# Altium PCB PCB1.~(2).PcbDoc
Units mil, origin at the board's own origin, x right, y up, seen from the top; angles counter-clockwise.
Board outline 6000 x 4000 mil, 2 copper layers (Top Layer, Bottom Layer); 19 components, 17 nets, 64 pads, 0 vias.
Unrouted connection lines stored in the file: 41.
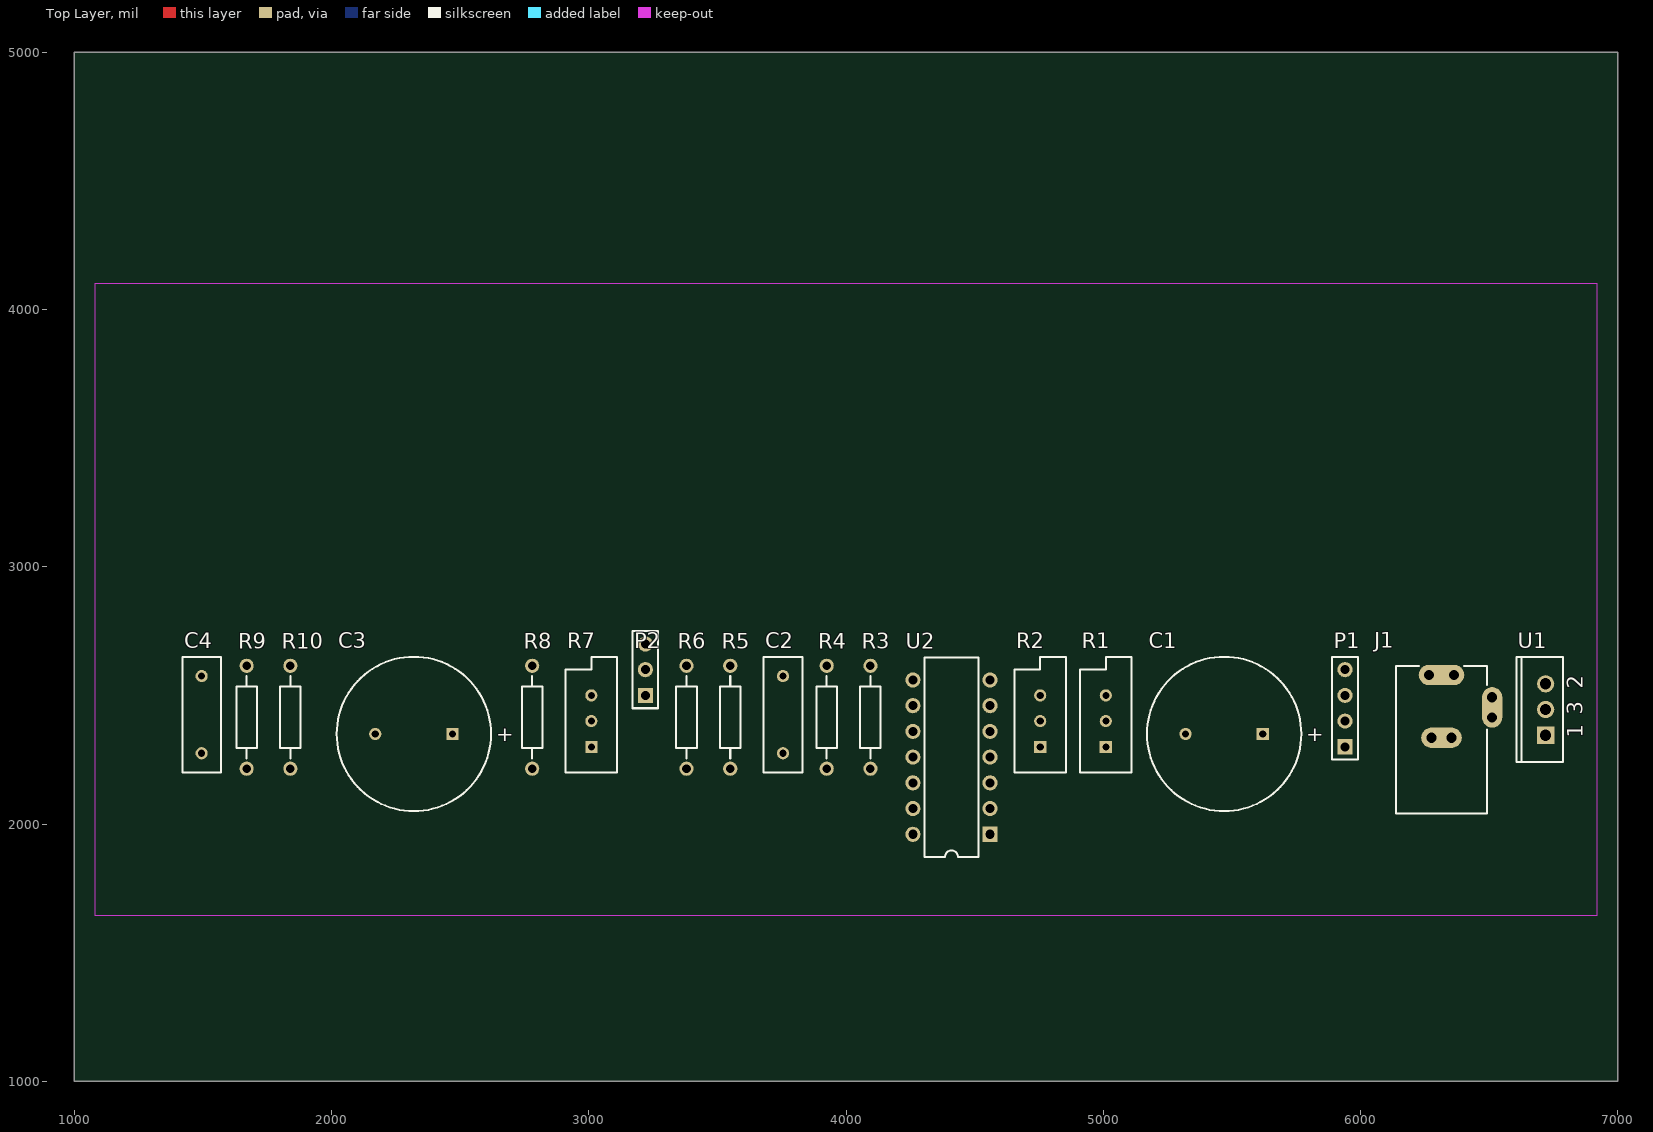
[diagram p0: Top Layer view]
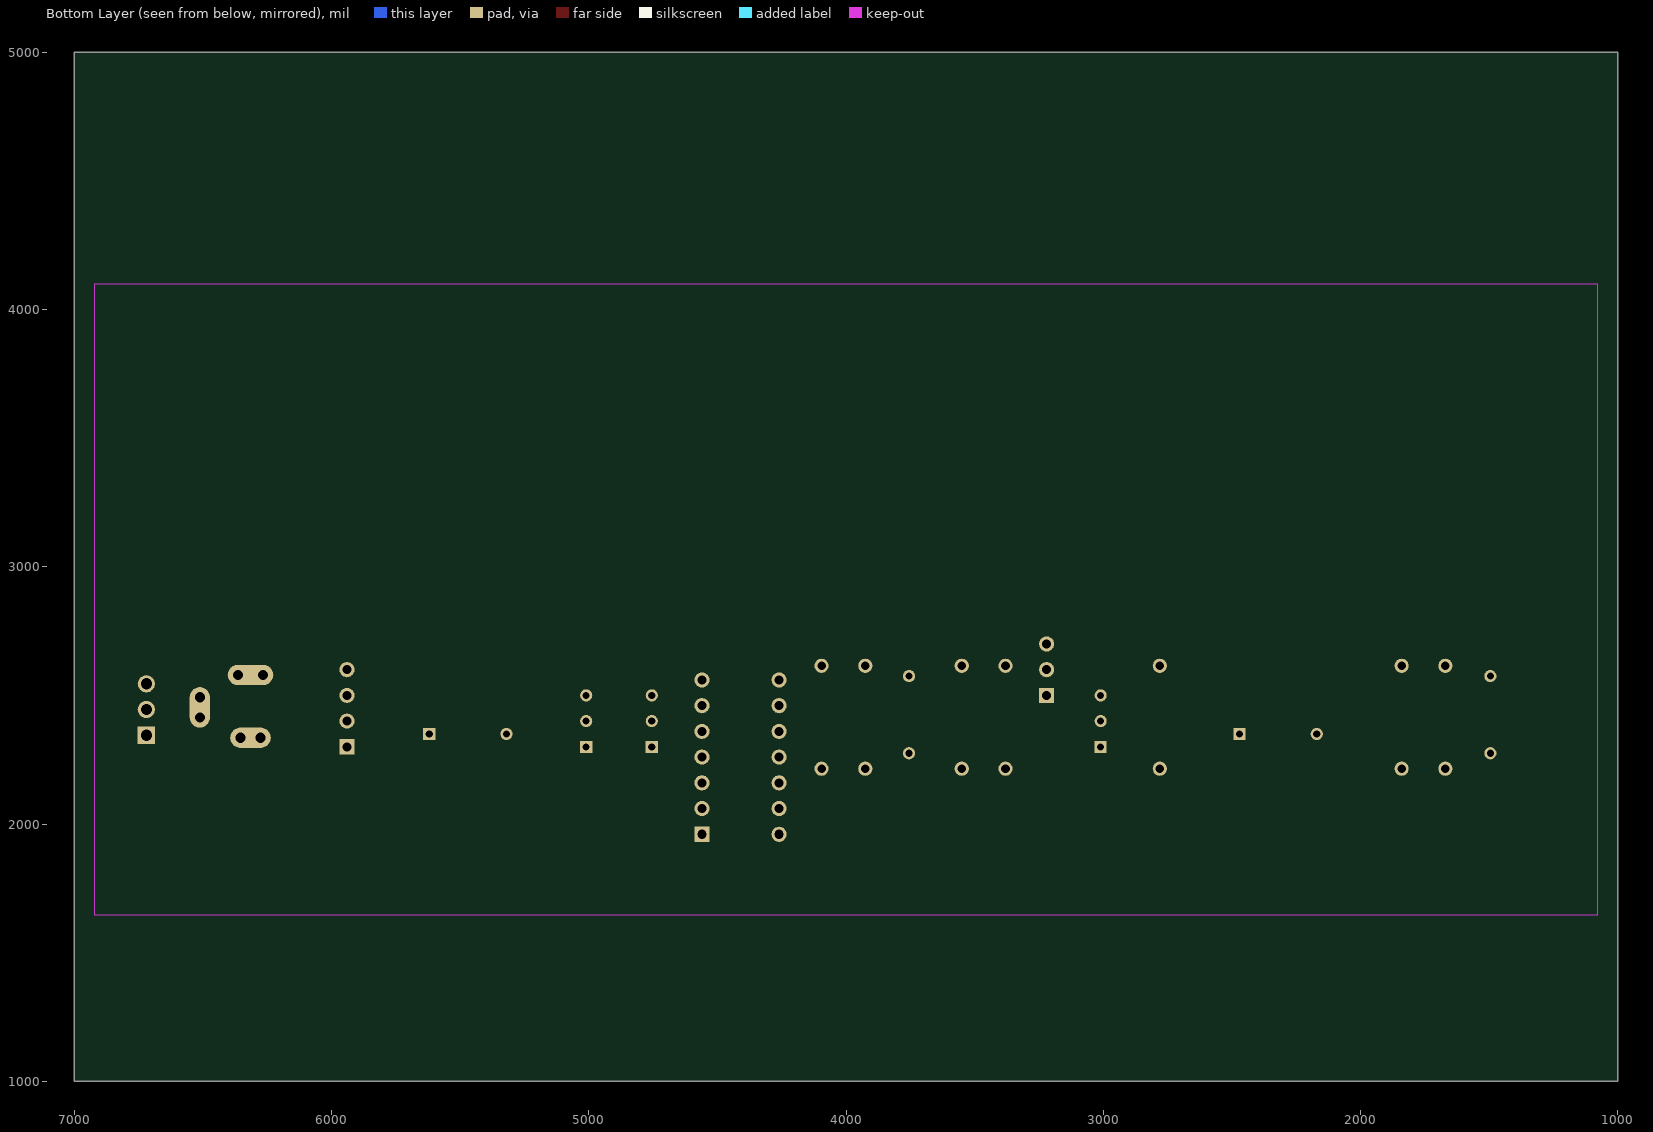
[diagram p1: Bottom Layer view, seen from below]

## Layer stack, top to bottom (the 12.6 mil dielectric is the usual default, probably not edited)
Top Layer: signal copper 1.4
Dielectric: dielectric 12.6, FR-4, Dk 4.8
Bottom Layer: signal copper 1.4

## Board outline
1000,1000 7000,1000 7000,5000 1000,5000

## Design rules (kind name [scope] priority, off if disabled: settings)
Clearance [All] p1: gap=10
ComponentClearance [All] p1: gap=10 collisioncheckmode=3 verticalgap=10
PolygonConnect [All] p1: connectstyle=Relief reliefconductorwidth=10 reliefentries=4 polygonreliefangle="90 Angle"
RoomDefinition Sheet1 [InComponentClass('Sheet1')] p1: confinementstyle=ConfineIn formatcopy=TRUE lockcomponents=FALSE outline 1410,1860 6880,1860 6880,2760 1410,2760
RoutingVias [All] p1: holewidth=28 width=50 viastyle="Through Hole" minholewidth=28 minwidth=50 maxholewidth=28 maxwidth=50
SolderMaskExpansion [All] p1: expansion=4
TestPointUsage [All] p1: valid=0 allowmultiple=FALSE
Testpoint [All] p1: side=15 testpointundercomponent=TRUE minsize=40 maxsize=100 preferedsize=60 minholesize=0 maxholesize=40 preferedholesize=32 testpointgrid=1 style=1023 order=0123456789
Width [All] p1: maxlimit=10 minlimit=10 preferedwidth=10
18 further rules are at their usual default settings.

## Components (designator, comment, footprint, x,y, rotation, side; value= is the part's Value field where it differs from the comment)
C1 "Cap Pol1" RB7.6-15 5470,2350 r0 top
C2 "Cap" RAD-0.3 3755,2425 r90 top
C3 "Cap Pol1" RB7.6-15 2320,2350 r0 top
C4 "Cap" RAD-0.3 1495,2425 r90 top
J1 "PWR2.5" KLD-0202 6315,2040 r90 top
P1 "Header 4" HDR1X4 5940,2300 r90 top
P2 "Header 3" HDR1X3 3220,2500 r90 top
R1 "RPot" VR5 5010,2400 r90 top
R2 "RPot" VR5 4755,2400 r90 top
R3 "Res2" AXIAL-0.4 4095,2415 r90 top
R4 "Res2" AXIAL-0.4 3925,2415 r90 top
R5 "Res2" AXIAL-0.4 3550,2415 r90 top
R6 "Res2" AXIAL-0.4 3380,2415 r90 top
R7 "RPot" VR5 3010,2400 r90 top
R8 "Res2" AXIAL-0.4 2780,2415 r90 top
R9 "Res2" AXIAL-0.4 1670,2415 r90 top
R10 "Res2" AXIAL-0.4 1840,2415 r90 top
U1 "L7812ABV" TO220ABN 6720,2445 r90 top
U2 "LM324AN" N14A 4410,2260 r90 top

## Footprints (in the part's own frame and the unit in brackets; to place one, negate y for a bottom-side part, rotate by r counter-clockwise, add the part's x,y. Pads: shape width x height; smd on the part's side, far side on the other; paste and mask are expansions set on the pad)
AXIAL-0.4 [mm] "Resistor; 2 Leads"
  round 1.4 hole 0.85: 1(-5.08,0) 2(5.08,0)
  silkscreen extent -4.06,-1.02 4.06,1.02
HDR1X3 [mm] "Connector; Header; 3 Position"
  rect 1.5x1.5 hole 0.9: 1(0,0)
  round 1.5 hole 0.9: 2(2.54,0) 3(5.08,0)
  silkscreen extent -1.27,-1.27 6.35,1.27
HDR1X4 [mm] "Connector; Header; 4 Position"
  rect 1.5x1.5 hole 0.9: 1(0,0)
  round 1.5 hole 0.9: 2(2.54,0) 3(5.08,0) 4(7.62,0)
  silkscreen extent -1.27,-1.27 8.89,1.27
KLD-0202 [mm] "DC Power Jack, 2.5mm, KLD Series, PCB Mount"
  oval 2x4.5 all layers, no hole: 1(13.7,0)
  round 1.5 hole 1: 1A(13.7,-1.25) 1B(13.7,1.25) 2A(7.5,-1) 2B(7.5,1) 3A(9.5,-5) 3B(11.5,-5)
  oval 2x4 all layers, no hole: 2(7.5,0)
  oval 4x2 all layers, no hole: 3(10.5,-5)
  silkscreen extent 0,-4.5 14.6,4.5
N14A [mm] "DIP; 14 Leads; Row Spacing 7.62 mm; Pitch 2.54 mm"
  rect 1.5x1.5 hole 0.9: 1(-7.62,-3.81)
  round 1.5 hole 0.9: 2(-5.08,-3.81) 3(-2.54,-3.81) 4(0,-3.81) 5(2.54,-3.81) 6(5.08,-3.81) 7(7.62,-3.81) 8(7.62,3.81) 9(5.08,3.81) 10(2.54,3.81) 11(0,3.81) 12(-2.54,3.81) 13(-5.08,3.81) 14(-7.62,3.81)
  silkscreen extent -9.85,-2.65 9.85,2.65
RAD-0.3 [mm] "Capacitor; 2 Leads"
  round 1.2 hole 0.7: 1(-3.81,0) 2(3.81,0)
  silkscreen extent -5.71,-1.91 5.71,1.91
RB7.6-15 [mm] "Polarized Capacitor (Radial); 2 Leads"
  rect 1.2x1.2 hole 0.7: 1(3.81,0)
  round 1.2 hole 0.7: 2(-3.81,0)
  silkscreen extent -7.62,-7.62 7.62,7.62
TO220ABN [mm] "TO, Thru-Hole, Vertical, Heatsink Mounted; 3 In-Line Leads; Pitch 2.54 mm; Pin sequence 1, 3, 2"
  rect 1.7x1.7 hole 1.1: 1(-2.54,0)
  round 1.7 hole 1.1: 2(2.54,0) 3(0,0)
  silkscreen extent -5.2,-1.7 5.2,2.9
VR5 [mm] "Potentiometer; 3 Leads"
  rect 1.2x1.2 hole 0.7: 1(-2.54,0)
  round 1.2 hole 0.7: 2(0,0) 3(2.54,0)
  silkscreen extent -5.08,-2.54 6.35,2.54

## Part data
C1 C3: "Polarized Capacitor (Radial)"
C2 C4: "Capacitor"
J1: "Low Voltage Power Supply Connector"
P1: "Header, 4-Pin"
P2: library part "Header 2", "Header, 2-Pin"
R1 R2 R7: "Potentiometer"
R3 R4 R5 R6 R8 R9 R10: "Resistor"
U1: "Precision 1A Regulator"
U2: "Low-Power Quad Operational Amplifier"

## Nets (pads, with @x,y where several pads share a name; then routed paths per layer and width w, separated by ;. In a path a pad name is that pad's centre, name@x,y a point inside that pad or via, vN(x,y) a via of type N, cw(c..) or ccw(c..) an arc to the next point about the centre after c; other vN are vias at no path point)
+5: C1.2 P1.1 P2.1 R1.2 U1.2 U2.4
GND: C1.1 C3.2 C4.1 J1.1 J1.1A J1.1B P1.4 P2.3 R1.1 R7.2 R8.2 R9.1 R10.2 U1.3 U2.11
NetC2_1: C2.1 R10.1 U2.5
NetC2_2: C2.2 R5.1
NetC3_1: C3.1 R4.1 U2.3
NetC4_2: C4.2 R6.1 U2.12
NetJ1_3: J1.3 J1.3A J1.3B
NetP1_2: P1.2 R6.2 R9.2
NetP1_3: P1.3 R1.3
NetP2_2: P2.2 R7.1 U2.8
NetR2_1: R2.1 R8.1 U2.2
NetR2_2: R2.2 R2.3 R3.2 U2.1
NetR3_1: R3.1 U2.9
NetR4_2: R4.2 U2.6 U2.7
NetR5_2: R5.2 U2.13 U2.14
NetR7_3: R7.3 U2.10
VCC: J1.2 J1.2A J1.2B U1.1

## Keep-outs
Keep-Out Layer:
  rectangle: 1080,1645 6920,4100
